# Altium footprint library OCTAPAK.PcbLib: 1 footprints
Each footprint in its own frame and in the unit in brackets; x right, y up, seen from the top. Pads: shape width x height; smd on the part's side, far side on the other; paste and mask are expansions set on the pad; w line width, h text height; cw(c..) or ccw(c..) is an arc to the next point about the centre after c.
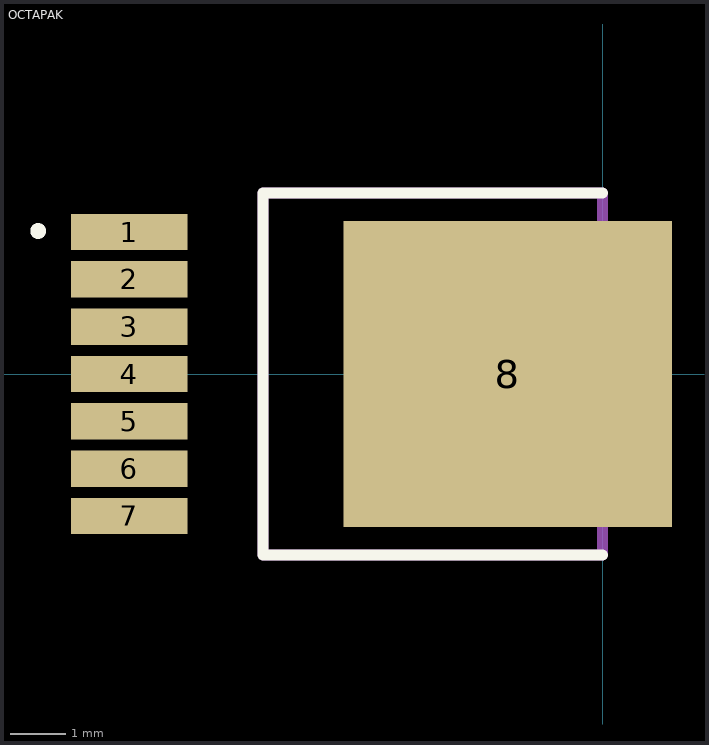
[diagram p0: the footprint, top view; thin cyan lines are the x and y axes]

## OCTAPAK [mm]
pads (8):
  rect 2.1x0.65 smd: 1(-8.5,2.55) 2(-8.5,1.7) 3(-8.5,0.85) 4(-8.5,0) 5(-8.5,-0.85) 6(-8.5,-1.7) 7(-8.5,-2.55)
  rect 5.9x5.5 smd: 8(-1.7,0)
L26-Silk Screen Top (Multiple PADS layers...):
  circle w0.2: c-10.136,2.568 r0.042
  lines w0.2: 0,-3.25 -6.1,-3.25 -6.1,3.25 0,3.25
L15 (Multiple PADS layers...):
  lines w0.2: -6.1,-3.25 0,-3.25 0,3.25 -6.1,3.25 -6.1,-3.25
